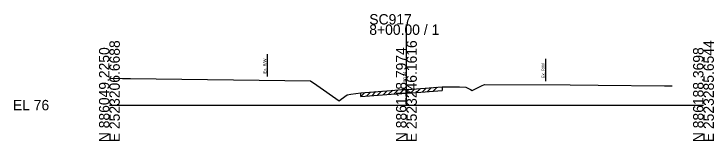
# Model space of a CAD drawing. Extents: x -26 to 218, y -10 to 12021.
# Drawn here: x -25.7 to 162.8, y 7990.3 to 8024.6 of the extents above; entities that cross this region are included whole.
import ezdxf

# ---------------------------------------------------------------- set-up
doc = ezdxf.new("R2010")
doc.units = 0
for name, color, linetype in [('RD_GPK_XS_Cell', 7, 'Continuous'), ('RD_XS_ExGround', 7, 'Continuous'), ('RD_XS_ExPaveRet', 7, 'Continuous'), ('RD_XS_ExRW', 7, 'Continuous'), ('RD_XS_TX_Elev_EX', 7, 'Continuous')]:
    doc.layers.add(name, color=color, linetype=linetype)

msp = doc.modelspace()

# ---------------------------------------------------------------- linework, layer by layer
at = {"layer": 'RD_GPK_XS_Cell'}
for p, q in [((80, 8000), (80, 8021.75)), ((0, 8000), (80, 8000)), ((80, 8000), (160, 8000))]:
    msp.add_line(p, q, dxfattribs=at)
at = {"layer": 'RD_XS_ExGround'}
for p, q in [((0, 8007.25), (3.5, 8007.22)), ((3.5, 8007.22), (4.22, 8007.21)), ((4.22, 8007.21), (5.69, 8007.19)), ((5.69, 8007.19), (54.17, 8006.58)), ((54.17, 8006.58), (55.88, 8005.36)), ((55.88, 8005.36), (61.86, 8001.16)), ((97.75, 8003.92), (100.18, 8005.16)), ((100.18, 8005.16), (101.07, 8005.6)), ((101.07, 8005.6), (124.09, 8005.44)), ((124.09, 8005.44), (131.6, 8005.4)), ((131.6, 8005.4), (149.48, 8005.21)), ((149.48, 8005.21), (151.54, 8005.2)), ((65.07, 8002.92), (67.71, 8003.3)), ((67.71, 8003.3), (75.88, 8003.97)), ((75.88, 8003.97), (78.8, 8004.17)), ((78.8, 8004.17), (80, 8004.24)), ((80, 8004.24), (81.59, 8004.34)), ((81.59, 8004.34), (89.59, 8004.9)), ((89.59, 8004.9), (94.29, 8004.89)), ((94.29, 8004.89), (96.04, 8004.88)), ((96.04, 8004.88), (97.25, 8004.18)), ((97.25, 8004.18), (97.75, 8003.92)), ((61.86, 8001.16), (62.41, 8001.57)), ((62.41, 8001.57), (64.03, 8002.75)), ((64.03, 8002.75), (65.07, 8002.92))]:
    msp.add_line(p, q, dxfattribs=at)
at = {"layer": 'RD_XS_ExPaveRet'}
for p, q in [((67.71, 8002.3), (68.8, 8003.39)), ((67.71, 8002.3), (67.71, 8003.3)), ((69.21, 8002.42), (70.3, 8003.51)), ((70.71, 8002.54), (71.8, 8003.63)), ((72.21, 8002.67), (73.3, 8003.76)), ((73.71, 8002.79), (74.8, 8003.88)), ((75.21, 8002.91), (76.3, 8004)), ((76.71, 8003.03), (77.79, 8004.1)), ((78.21, 8003.13), (79.28, 8004.2)), ((78.8, 8003.17), (80, 8003.24)), ((79.71, 8003.23), (80.78, 8004.29)), ((80, 8003.24), (81.59, 8003.34)), ((81.21, 8003.32), (82.28, 8004.39)), ((81.59, 8003.34), (89.59, 8003.9)), ((82.71, 8003.42), (83.79, 8004.49)), ((84.21, 8003.52), (85.29, 8004.6)), ((85.71, 8003.63), (86.79, 8004.71)), ((87.21, 8003.74), (88.29, 8004.81)), ((89.59, 8004.9), (89.59, 8003.9)), ((67.71, 8002.3), (75.88, 8002.97)), ((75.88, 8002.97), (78.8, 8003.17))]:
    msp.add_line(p, q, dxfattribs=at)
at = {"layer": 'RD_XS_ExRW'}
for p, q in [((42.5, 8013.73), (42.5, 8007.73)), ((117.5, 8012.49), (117.5, 8006.49))]:
    msp.add_line(p, q, dxfattribs=at)

# ---------------------------------------------------------------- texts
at = {"layer": 'RD_GPK_XS_Cell'}
for s, p in [('SC917', (70, 8021.75)), ('8+00.00 / 1', (70, 8018.95)), ('EL 76', (-26, 7998.6))]:
    msp.add_text(s, height=2.8, dxfattribs=at).set_placement(p)
for s, p in [('E 2523206.6688', (2.8, 7990)), ('E 2523246.1616', (82.8, 7990)), ('E 2523285.6544', (162.8, 7990)), ('N 886049.2250', (0, 7990)), ('N 886118.7974', (80, 7990)), ('N 886188.3698', (160, 7990))]:
    msp.add_text(s, height=2.8, rotation=90, dxfattribs=at).set_placement(p)
at = {"layer": 'RD_XS_ExRW'}
for p in [(42.25, 8008.52), (117.25, 8007.28)]:
    msp.add_text('Ex. R/W ', height=0.8, rotation=90, dxfattribs=at).set_placement(p)
at = {"layer": 'RD_XS_TX_Elev_EX'}
msp.add_text('80.24', height=0.8, rotation=90, dxfattribs=at).set_placement((79.9, 8006.24))

doc.saveas('drawing.dxf')
